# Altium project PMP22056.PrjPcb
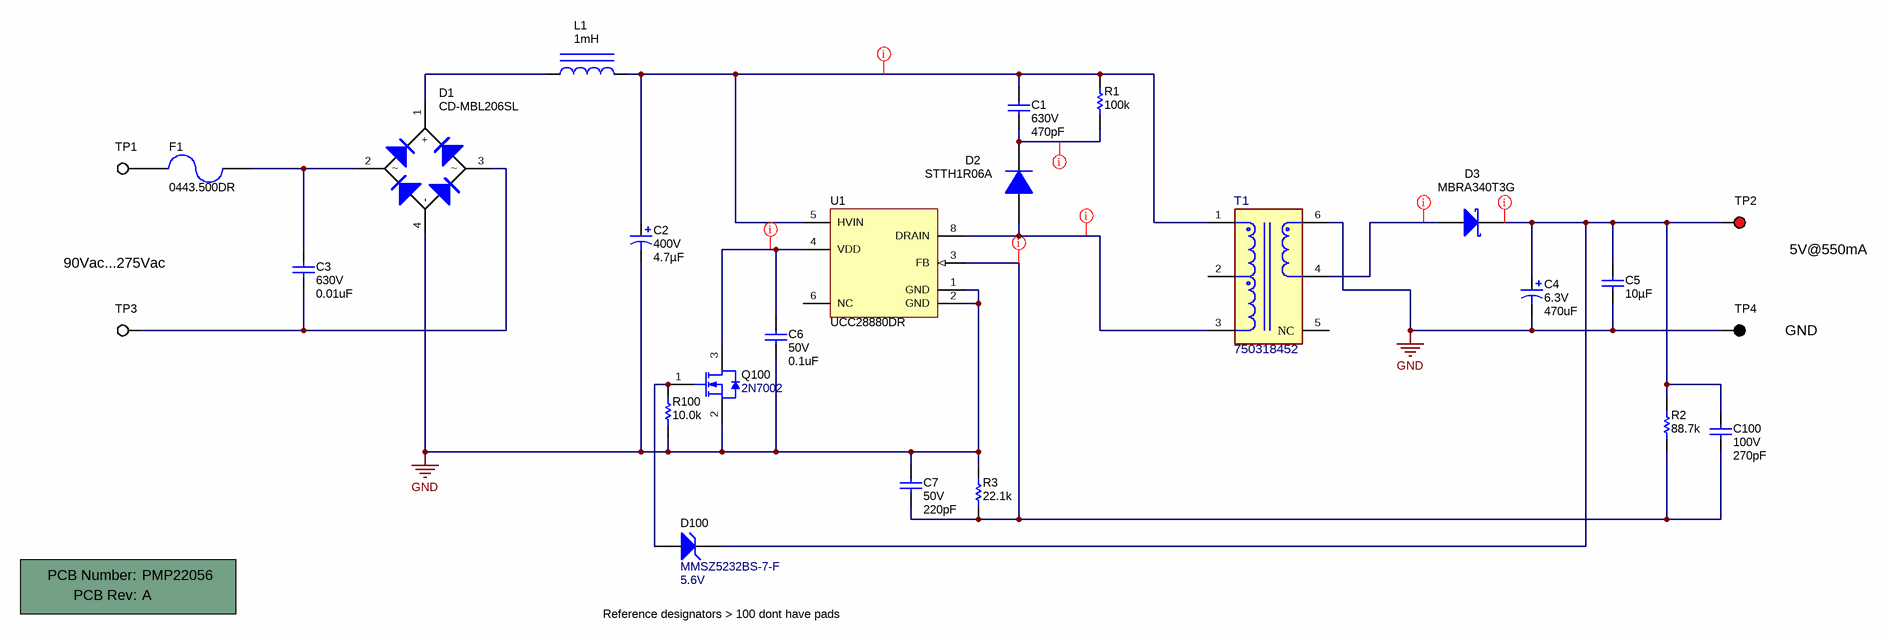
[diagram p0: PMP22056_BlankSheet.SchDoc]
CopyrightYear: 2019; PCB_Layout: S. Abedin; PCB_Rev: A; PRJ_Customer: Public Release; PRJ_Engineer: S. Abedin; PRJ_Number: PMP22056; SCH_Rev: A; TechSupport: http://www.ti.com/support; TID: N/A
1 sheet, 26 parts. Net scope: global (net labels, ports and power ports of the same name join across sheets).
Board file: PMP22056_PCB.PcbDoc

## Sheet PMP22056_BlankSheet.SchDoc
size 431 x 279 mm; Date: Not shown in title block; ApprovedBy: Not shown in title block; CheckedBy: Not shown in title block; Author: Not shown in title block; CompanyName: Not shown in title block; Engineer: Not shown in title block; Organization: Not shown in title block; Address1: Not shown in title block; Address2: Not shown in title block; Address3: Not shown in title block; Address4: Not shown in title block; DocumentNumber: 2; Revision: Use project parameter SCH_Rev; SheetNumber: 2; SheetTotal: 3; PageSetup: Record=PageOptions¦CenterHorizontal=True¦CenterVertical=True¦PrintScale=1.00¦XCorrection=1.00¦YCorrection=1.00¦PrintKind=0¦BorderSize=5000000¦LeftOffset=0¦BottomOffset=0¦Orientation=2¦PaperLength=1000¦PaperWidth=1000¦Scale=100¦PaperSource=15¦PrintQuality=600¦MediaType=1¦DitherType=10¦PaperKind=Letter¦PrintScaleMode=1

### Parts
!PCB1  Printed Circuit Board  (value not drawn)  (mechanical)
C1  VDC_V: 630V  ValueDisplayed: 470pF  [1206M]  (hidden comment: C3216C0G2J471J085AA)
C2  VDC_V: 400V  ValueDisplayed: 4.7µF  [AX_800x900]  (hidden comment: 400AX4.7MEFC8X9)
C3  VDC_V: 630V  ValueDisplayed: 0.01uF  [2220_330_N]  (hidden comment: LDEPD2100KA5N00)
C4  VDC_V: 6.3V  ValueDisplayed: 470uF  [7343-20]  (hidden comment: 6TPE470MAZU)
C5  ValueDisplayed: 10µF  [0805_HV]  (hidden comment: C2012X7R0J106M125AB)
C6  VDC_V: 50V  ValueDisplayed: 0.1uF  [0402S]  (hidden comment: CGA2B3X7R1H104K050BB)
C7  VDC_V: 50V  ValueDisplayed: 220pF  [0402S]  (hidden comment: CGA2B2X8R1H221K050BA)
C100  VDC_V: 100V  ValueDisplayed: 270pF  [0402]  (hidden comment: GRM155R72A271KA01D)
D1  CD-MBL206SL  [CD-MBL2xxS]
D2  STTH1R06A  [SMA]
D3  MBRA340T3G  [SMA]
D100  MMSZ5232BS-7-F  value 5.6V  [SOD-323]
F1  0443.500DR  [FUSE_0443]
L1  value 1mH  [IND_WE-TI_XS]  (hidden comment: 7447462102)
Q100  2N7002  [SOT-23]
R1  ValueDisplayed: 100k  [0603]  (hidden comment: CRCW0603100KJNEA)
R2  ValueDisplayed: 88.7k  [0603]  (hidden comment: CRCW060388K7FKEA)
R3  ValueDisplayed: 22.1k  [0603]  (hidden comment: CRCW060322K1FKEA)
R100  ValueDisplayed: 10.0k  [0402]  (hidden comment: RT0402BRD0710KL)
T1  750318452  [FP-750318452_XFMR_10MM16_8MM26_PTH_6-Recommended_Land Pattern]
TP1  5002  [Keystone5002]  (value not drawn)
TP2  5000  [Keystone5000]  (value not drawn)
TP3  5002  [Keystone5002]  (value not drawn)
TP4  5001  [Keystone5001]  (value not drawn)
U1  UCC28880DR  [D0007A_N]

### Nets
GND: C2.2(-) C4.2(-) C5.2 C6.2 C7.1 D1.4(-) Q100.2(S) R3.2 R100.1 T1.6 TP4.1 U1.1(GND) U1.2(GND)
NetC1_1: C1.1 C2.1(+) L1.2 R1.2 T1.1 U1.5(HVIN)
NetC1_2: C1.2 D2.1(K) R1.1
NetC3_1: C3.1 D1.2 F1.1
NetC3_2: C3.2 D1.3 TP3.1
NetC4_1: C4.1(+) C5.1 C100.1 D3.1(K) D100.1(K) R2.2 TP2.1
NetC6_1: C6.1 Q100.3(D) U1.4(VDD)
NetC7_2: C7.2 C100.2 R2.1 R3.1 U1.3(FB)
NetD1_1: D1.1(+) L1.1
NetD2_2: D2.2(A) T1.3 U1.8(DRAIN)
NetD3_2: D3.2(A) T1.4
NetD100_2: D100.2(A) Q100.1(G) R100.2
NetF1_2: F1.2 TP1.1

Not connected (* = marked no-connect by the designer): T1 2 5(NC); U1 6(NC)

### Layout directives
rule Clearance Constraint [Clearance = 40mil]: NetC1_1, NetC1_2, NetD2_2
rule Clearance Constraint [Clearance = 10mil]: NetC4_1, NetC6_1, NetC7_2, NetD3_2

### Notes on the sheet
- 90Vac...275Vac
- 5V@550mA
- GND
- Reference designators > 100 dont have pads

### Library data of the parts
!PCB1 = CMP-0003618-2: Manufacturer: Any; PartNumber: PMP22056
C1 = CMP-0008645-1: CAP, CERM, 470 pF, 630 V, +/- 5%, C0G/NP0, 1206; Manufacturer: TDK; TaMin_C: -55°C; Polarized: N; SizeAreaWB_mm2: 10.92; Value1: Unknown; U/M: EA; Value: 470pF; TaMax_C: 125°C; SizeZ_mm: 1.35; SizeX_mm: 3.2; SizeY_mm: 1.6; Cap_Case: 1206; SizeArea_mm2: 5.12; AEC Category: Q200
C2 = CMP-0860315-1: CAP, AL, 4.7 µF, 400 V, +/- 20%, TH; Manufacturer: Rubycon; AEC Qualified: N; U/M: EA; TaMax_C: 105°C; SizeZ_mm: 10.5; Polarized: Y; CompType: Capacitor; SizeAreaWB_mm2: 100; AEC Category: Q200; Value: 4.7uF; SizeX_mm: 8; SizeArea_mm2: 64; Cap_Case: 8x9mm; TaMin_C: -40°C
C3 = CMP-0012521-1: CAP, Film, 0.01 uF, 630 V, +/- 10%, AEC-Q200 Grade 1, 2220 SMD; Manufacturer: Kemet; TaMin_C: -55°C; Polarized: N; SizeAreaWB_mm2: 53.9; Value1: Unknown; U/M: EA; Value: 0.01uF; TaMax_C: 125°C; SizeZ_mm: 3.3; SizeX_mm: 5.7; SizeY_mm: 5; Cap_Case: 2220; SizeArea_mm2: 28.5; AEC Qualified: Y; Cap_F: 10nF; AEC Grade: 1; AEC Category: Q200
C4 = CMP-0012638-4: CAP, Tantalum Polymer, 470 uF, 6.3 V, +/- 20%, 0.035 ohm, 7343-20 SMD; Manufacturer: Panasonic; TaMin_C: -55°C; ESR_ohm: 0.035; Polarized: Y; SizeAreaWB_mm2: 58.59; Value: 470uF; TaMax_C: 105°C; SizeZ_mm: 2; SizeX_mm: 7.3; SizeY_mm: 4.3; SizeArea_mm2: 31.39; CompType: Capacitor; AEC Qualified: N; Cap_F: 470µF; IRMS_A: 1.7A; AEC Category: Q200
C5 = C2012X7R0J106M125AB: CAP, CERM, 10 µF, 6.3 V, +/- 20%, X7R, 0805; Manufacturer: TDK; Polarized: N; CompType: Capacitor; Value: 10uF; U/M: EA; Cap_F: 0.00001; Tolerance_%: 20; Value1: Unknown; VDC_V: 6.3; Value2: 6.3V; TaMin_C: -55; TaMax_C: 125; Cap_Case: 0805
C6 = CMP-0006325-1: CAP, CERM, 0.1 uF, 50 V, +/- 10%, X7R, AEC-Q200 Grade 1, 0402; Manufacturer: TDK; TaMin_C: -55°C; ESR_ohm: 0.039064; Polarized: N; SizeAreaWB_mm2: 3; Value1: 0.039064 ohm; U/M: EA; Value: 0.1uF; TaMax_C: 125°C; SizeZ_mm: 0.6; SizeX_mm: 1; SizeY_mm: 0.5; Cap_Case: 0402; AEC Qualified: Y; Cap_F: 100nF; IRMS_A: 814.669mA; AEC Category: Q200
C7 = CMP-0084239-1: CAP, CERM, 220 pF, 50 V,+/- 10%, X8R, AEC-Q200 Grade 0, 0402; Manufacturer: TDK; TaMin_C: -55°C; Polarized: N; SizeAreaWB_mm2: 3; U/M: EA; Value: 220pF; TaMax_C: 150°C; SizeZ_mm: 0.6; SizeX_mm: 1; SizeY_mm: 0.5; Cap_Case: 0402; AEC Qualified: Y; AEC Grade: 0; AEC Category: Q200
C100 = CMP-0006705-1: CAP, CERM, 270 pF, 100 V, +/- 10%, X7R, 0402; Manufacturer: MuRata; TaMin_C: -55°C; Polarized: N; SizeAreaWB_mm2: 3; Value1: Unknown; U/M: EA; Value: 270pF; TaMax_C: 125°C; SizeZ_mm: 0.6; SizeX_mm: 1; SizeY_mm: 0.5; AEC Category: Q200
D1 = CMP-0067544-2: Diode, P-N-Bridge, 600 V, 2 A, 5.8x5.3mm; Manufacturer: Bourns; SizeAreaWB_mm2: 47.092; SizeX_mm: 5.72; AEC Qualified: N; Io_A: 2A; Vf_V: 9.6dV; Value2: 0.96V; SizeZ_mm: 1.35; SizeArea_mm2: 23.452; AEC Category: Q101; RJC_CperW: 15.0; Value: 600V; TJmax_C: 175°C; SizeY_mm: 4.1
D2 = STTH1R06A: Diode, Ultrafast, 600 V, 1 A, SMA; Manufacturer: ST Microelectronics; U/M: EA; Vf_V: 1; Value: 600V; Value1: 1A; Value2: 1V; Vr_V: 600; TJmax_C: 175; RJC_CperW: 30
D3 = MBRA340T3G: Diode, Schottky, 40 V, 3 A, SMA; Manufacturer: ON Semiconductor; U/M: EA; Vf_V: 0.415; Value: 40V; Value1: 3A; Value2: 0.415V; Io_A: 3; Vr_V: 40; RJC_CperW: 15
D100 = CMP-0005855-1: Diode, Zener, 5.6 V, 200 mW, SOD-323; Manufacturer: Diodes Inc.; Power_W: 200mW; SizeAreaWB_mm2: 8.695; Value1: 0.2W; RJA_CperW: 350; U/M: EA; SizeZ_mm: 1; SizeX_mm: 2.7; SizeY_mm: 1.35; SizeArea_mm2: 3.645; AEC Category: Q101
F1 = CMP-0003466-1: Fuse, 0.5 A, 250VAC/VDC, SMD; Manufacturer: Littelfuse; Irating_A: 500mA; Interrupt_AC: 50A; Interrupt_DC: 250A; VAC_V: 250V; Rtyp_Ohm: 0.6; MeltingTyp: 1.61
L1 = 7447462102: Inductor, Unshielded Drum Core, Ferrite, 1 mH, 0.25 A, 4.38 ohm, TH; Manufacturer: Wurth Elektronik eiSos; Ind_H: 1.0E-3; Imax_A: 0.25; Irms: 0.25A @ 40C rise; Isat: 0.27A @ 10% inductance drop; DCR_ohm: 4.38; Value2: 0.25A
Q100 = CMP-0000768-1: MOSFET, N-CH, 60 V, 115 A, SOT-23; Alternate Manufacturer: None; Manufacturer: Fairchild Semiconductor; SizeZ_mm: 1.1; ChType: N; VdsMax_V: 60V; SizeX_mm: 2.5; SizeY_mm: 3; Vgs_V: 20V; Value: 60V; SizeArea_mm2: 7.5; AEC Category: Q101; IdsMax_A: 115A; SizeAreaWB_mm2: 14; U/M: EA
R1 = CMP-0025698-1: RES, 100 k, 5%, 0.1 W, 0603; Manufacturer: Vishay-Dale; Power_W: 100mW; TempCo: 200 ppm/C; U/M: EA; Value: 100k; EIA_Code: E24; SizeX_mm: 1.6; SizeY_mm: 0.8; SizeZ_mm: 1; Value2: 0.1W; SizeArea_mm2: 1.28; VDC_V: 75V; AEC Category: Q200
R2 = CRCW060388K7FKEA: RES, 88.7 k, 1%, 0.1 W, 0603; Manufacturer: Vishay-Dale; CompType: Resistor; Value: 88.7k; Res_ohm: 88700; Value_Code: 88k7; Tolerance_%: 1; Power_W: 0.1; Value2: 0.1W; VDC_V: 75; TempCo: 100 ppm/C; EIA_Code: E96; U/M: EA
R3 = CRCW060322K1FKEA: RES, 22.1 k, 1%, 0.1 W, 0603; Manufacturer: Vishay-Dale; CompType: Resistor; Value: 22.1k; Res_ohm: 22100; Value_Code: 22k1; Tolerance_%: 1; Power_W: 0.1; Value2: 0.1W; VDC_V: 75; TempCo: 100 ppm/C; EIA_Code: E96; U/M: EA
R100 = CMP-0065360-1: RES, 10.0 k, .1%, .0625 W, 0402; Manufacturer: Yageo America; Power_W: 62.5mW; TempCo: 25 ppm/C; Value_Code: 10k0; U/M: EA; Value: 10.0k; EIA_Code: E192; Tolerance_%: 0.1%; Res_ohm: 10k; SizeX_mm: 1.0; SizeY_mm: 0.5; SizeZ_mm: 0.6; Value2: .0625W; VDC_V: 50V; AEC Category: Q200
T1 = CMP-0087346-1: TRANSFORMER 10mH, Leak 150uH, 20:1, 50kHz, 1500VAC; Manufacturer: Wurth Electronics; Ns1toNp: 1:1/20:1; SizeZ_mm: 9.78mm; Rsec1_ohm: 0.205; DCR_ohm: 50.85
TP1 TP3 = 5002: Test Point, Miniature, White, TH; Manufacturer: Keystone; CompType: Test Point Loop; U/M: EA
TP2 = 5000: Test Point, Miniature, Red, TH; Manufacturer: Keystone; CompType: Test Point Loop; U/M: EA
TP4 = 5001: Test Point, Miniature, Black, TH; Manufacturer: Keystone; CompType: Test Point Loop; U/M: EA
U1 = UCC28880DR: 700-V Lowest Quiescent Current Off-Line Switcher, D0007A; Alternate Manufacturer: None; Manufacturer: Texas Instruments; SymbolCreator: a0411947; CompType: IC; U/M: EA

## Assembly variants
001: not fitted C7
